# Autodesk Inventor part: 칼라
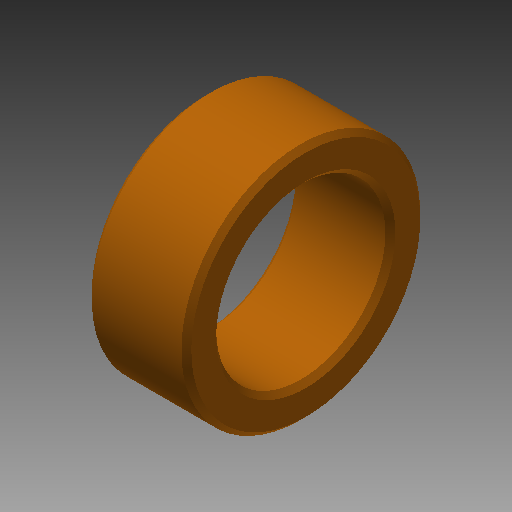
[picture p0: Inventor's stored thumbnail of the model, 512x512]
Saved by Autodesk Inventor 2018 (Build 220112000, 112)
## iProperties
Created: 2015-09
Part Number: 칼라
Material: 강철, 연강
Document SubType Name: Modeling
Designer: mduedu
Density: 7.86 g/cm^3
Description: 외주 가공
Mass: 17.8983 g
Surface Area: 15.6581 cm^2
Volume: 2.27713 cm^3
Appearance: 주황색
Author: mduedu
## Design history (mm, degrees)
sketch "스케치1"
  geometry: C1 r 12 at (0, 0); C2 r 8.5 at (0, 0); 1 further point
  constraints: 2 centre point, 2 coincident
  dimensions: "d0" = 24 diameter of C1; "d2" = 17 diameter of C2
extrude "돌출1" new body sketch "스케치1" distance "d3" = 10; taper "d4" = 0 deg
chamfer "모따기1" distance "d5" = 0.5; stored, may be unused: second distance "d6" = 2, angle "d7" = 45 deg
node "솔리드1"
